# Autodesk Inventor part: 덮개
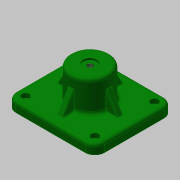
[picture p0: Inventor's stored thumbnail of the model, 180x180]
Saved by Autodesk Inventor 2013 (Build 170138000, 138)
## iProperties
Created: 2017-08
Part Number: 덮개
Material: 알루미늄 6061
Document SubType Name: Modeling
Designer: mduedu
Density: 1 g/cm^3
Author: mduedu
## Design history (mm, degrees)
sketch "스케치1"
  geometry: L1 (46, -41)-(-46, -41); L2 (-46, -41)-(-46, 41); L3 (-46, 41)-(46, 41); L4 (46, 41)-(46, -41); 1 further point
  constraints: 8 end point, 2 parallel, 1 horizontal, 1 perpendicular
  dimensions: "d0" = 92 distance of L2.end L3.end; "d2" = 82 distance of L1.end L2.end; "d3" = 41 distance from line of L3 point (0, 0) (= 0.5 x d2); "d4" = 46 distance from line of point (0, 0) L4 (= 0.5 x d0)
extrude "돌출1" new body sketch "스케치1" distance "d5" = 10; taper "d6" = 0 deg
sketch "스케치2"
  geometry: C1 r 20 at (0, 0); 1 further point
  constraints: 1 centre point, 1 coincident
  dimensions: "d55" = 40 diameter of C1
extrude "돌출2" join sketch "스케치2" distance "d9" = 32; taper "d10" = 0 deg
sketch "스케치3"
  geometry: L1 (-26, -26)-(26, -26); L2 (26, -26)-(26, 26); L3 (26, 26)-(-26, 26); L4 (-26, 26)-(-26, -26); L5 (-26, -26)-(26, 26); L6 (26, -26)-(-26, 26); 1 further point
  constraints: 12 end point, 2 midpoint, 2 parallel, 2 perpendicular, 1 horizontal
  dimensions: "d11" = 52 distance of L3.end L2.end
extrude "돌출3" join sketch "스케치3" distance "d12" = 6; taper "d13" = 0 deg
sketch "스케치4"
  geometry: L1 (-17, -17)-(17, -17); L2 (17, -17)-(17, 17); L3 (17, 17)-(-17, 17); L4 (-17, 17)-(-17, -17); L5 (-17, -17)-(17, 17); L6 (17, -17)-(-17, 17); 1 further point
  constraints: 12 end point, 2 midpoint, 2 parallel, 2 perpendicular, 1 horizontal
  dimensions: "d14" = 34 distance of L2.end L3.end
extrude "돌출4" cut sketch "스케치4" distance "d16" = 5; taper "d17" = 0 deg
sketch "스케치5"
  geometry: C1 r 9 at (0, 0); 1 further point
  constraints: 1 centre point, 1 coincident
  dimensions: "d18" = 18 diameter of C1
extrude "돌출5" cut sketch "스케치5" distance "d19" = 34; taper "d20" = 0 deg
sketch "스케치6"
  geometry: 2 further points
  constraints: 1 coincident
hole "구멍1" sketch "스케치6" at (0, 0) diameter "d21" = 5.917; stored, may be unused: countersink angle "d25" = 90 deg, drill point angle "d27" = 118 deg; dims "d22" = 6, "d23" = 14, "d24" = 2, "d26" = 8
fillet "모깎기1" dims "d36" = 10
fillet "모깎기3" dims "d38" = 3
fillet "모깎기4" dims "d39" = 3
fillet "모깎기5" dims "d40" = 3
chamfer "모따기1" distance "d41" = 1; stored, may be unused: second distance "d42" = 2, angle "d43" = 45 deg
fillet "모깎기6" dims "d44" = 3
fillet "모깎기7" dims "d45" = 3
fillet "모깎기8" dims "d46" = 3
sketch "스케치8"
  geometry: A1 r 10 centre (-36, -31) between (-46, -31) and (-36, -41) reference; A2 r 10 centre (-36, 31) between (-36, 41) and (-46, 31) reference; A3 r 10 centre (36, 31) between (46, 31) and (36, 41) reference; A4 r 10 centre (36, -31) between (36, -41) and (46, -31) reference; 5 further points
  constraints: 4 coincident
sketch "스케치9"
  geometry: 4 further points
  constraints: 4 other
hole "구멍3" sketch "스케치9" at (-36, -31), (-36, 31), (36, 31), (36, -31) diameter "d48" = 4.5; stored, may be unused: countersink angle "d52" = 90 deg, drill point angle "d54" = 0 deg; dims "d49" = 6, "d50" = 8, "d51" = 4.6, "d53" = 8
sketch "스케치10"
  geometry: L1 (-7, 40)-(-2.958, 40) reference; L2 (-2.958, 40)-(-2.958, 33) reference; L3 (-2.958, 33)-(-6, 33) reference; L4 (-9, 30)-(-9, -1) reference; L5 (-9, -1)-(-14, -1) reference; L6 (-17, -4)-(-17, -6) reference; L7 (-17, -6)-(-25, -6) reference; L8 (-25, -6)-(-26, -5) reference; L9 (-26, -5)-(-26, 0) reference; L10 (-26, 0)-(-46, 0) reference; L11 (-46, 0)-(-46, 7) reference; L12 (-43, 10)-(-23, 10) reference; L13 (-20, 13)-(-20, 39) reference; L14 (-17, 42)-(-7, 42) reference; L15 (-7, 42)-(-7, 40) reference; L16 (2.958, 40)-(7, 40) reference; L17 (7, 40)-(7, 42) reference; L18 (7, 42)-(17, 42) reference; L19 (20, 39)-(20, 13) reference; L20 (23, 10)-(43, 10) reference; L21 (46, 7)-(46, 0) reference; L22 (46, 0)-(26, 0) reference; L23 (26, 0)-(26, -5) reference; L24 (26, -5)-(25, -6) reference; L25 (25, -6)-(17, -6) reference; L26 (17, -6)-(17, -4) reference; L27 (14, -1)-(9, -1) reference; L28 (9, -1)-(9, 30) reference; L29 (6, 33)-(2.958, 33) reference; L30 (2.958, 33)-(2.958, 40) reference; L31 (31.547, 10)-(20, 30); A1 r 3 centre (-6, 30) between (-6, 33) and (-9, 30) reference; A2 r 3 centre (-14, -4) between (-14, -1) and (-17, -4) reference; A3 r 3 centre (-43, 7) between (-43, 10) and (-46, 7) reference; A4 r 3 centre (-23, 13) between (-23, 10) and (-20, 13) reference; A5 r 3 centre (-17, 39) between (-17, 42) and (-20, 39) reference; A6 r 3 centre (17, 39) between (20, 39) and (17, 42) reference; A7 r 3 centre (23, 13) between (20, 13) and (23, 10) reference; A8 r 3 centre (43, 7) between (46, 7) and (43, 10) reference; A9 r 3 centre (14, -4) between (17, -4) and (14, -1) reference; A10 r 3 centre (6, 30) between (9, 30) and (6, 33) reference; 1 further point
  constraints: 2 end point, 2 point on line
  dimensions: "d56" = 20 distance from line of L31.end L20; "d57" = 120 deg angle of L31 L20
feature "리브1" sketch "스케치10" dims "d58" = 1, "d59" = 6, "d60" = 0, "d61" = 0, "d62" = 1, "d63" = 1
fillet "모깎기9" dims "d64" = 1
fillet "모깎기10" dims "d65" = 1
node "솔리드1"
pattern_circular "원형 패턴1" dims "d67" = 360 deg
node "절단 모서리 투영1"
